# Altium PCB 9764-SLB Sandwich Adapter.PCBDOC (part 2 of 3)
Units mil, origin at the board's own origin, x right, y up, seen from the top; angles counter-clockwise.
Board outline 5593.84 x 1511.98 mil, 8 copper layers (Top Layer, MidLayer1, MidLayer2, MidLayer3, MidLayer4, MIdLayer5, MidLayer6, Bottom Layer); 137 components, 228 nets, 1508 pads, 0 vias.
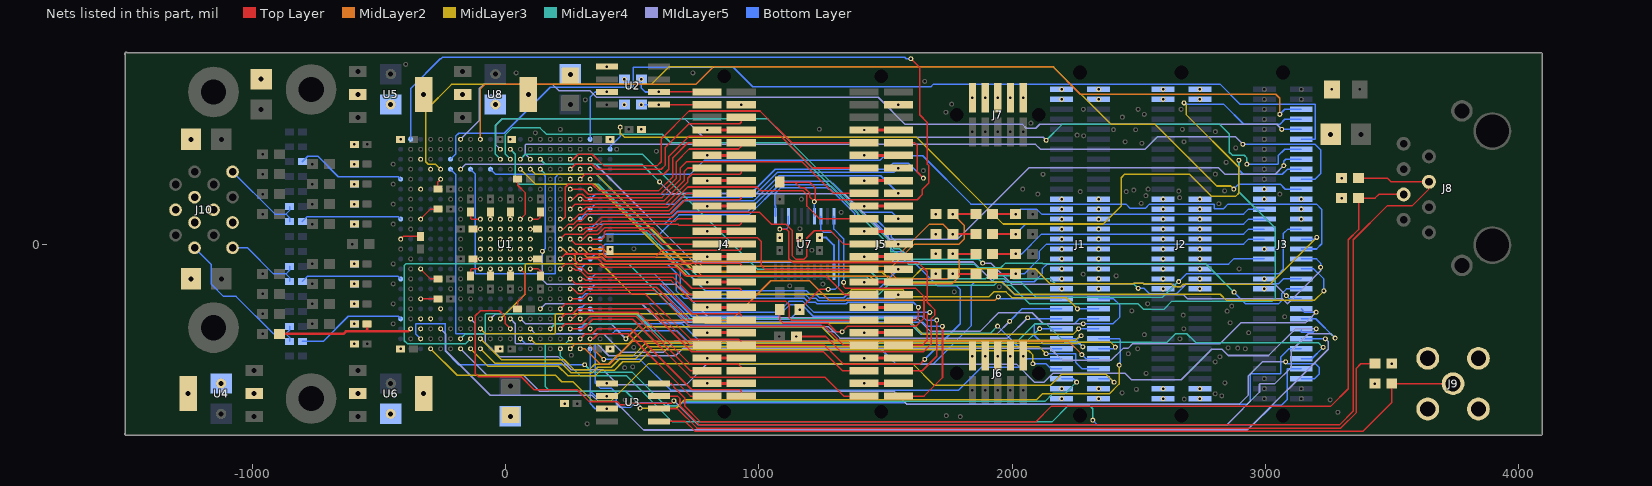
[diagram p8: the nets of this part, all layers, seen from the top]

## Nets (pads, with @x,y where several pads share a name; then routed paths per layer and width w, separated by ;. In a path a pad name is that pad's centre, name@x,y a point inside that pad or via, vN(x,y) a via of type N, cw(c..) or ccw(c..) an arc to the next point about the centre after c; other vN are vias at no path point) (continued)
AVCCAUX8: C28.1 L22.1 U1.B20 | length 557.6
  Top Layer w10: L22.1@-891.73,-354.33 -639.76,-354.33 -629.92,-344.49 -551.18,-344.49 ; C28.1@-545.87,-314.96 -545.87,-339.17 -551.18,-344.49 ; U1.B20@-374.02,-334.65 -383.86,-344.49 -551.18,-344.49
B: C43.1 C44.1 J10.1 | length 350.8
  Bottom Layer w6: J10.1@-1076.85,285 -909.96,118.11 -866.14,118.11 ; C43.1@-851.77,88.58 -851.77,103.74 -866.14,118.11 ; C44.1@-851.77,147.64 -851.77,132.48 -866.14,118.11
BCO+: pad.0@1765.75,39.37 R7.2 R11.2 U1.Y12 | length 1619.5
  Top Layer w8: R11.2@1765.75,39.37 R7.2@1856.3,39.37
  MidLayer2 w6: U1.Y12@334.65,-19.69 385.83,-19.69 405.51,-39.37 748.03,-39.37 777.56,-68.9 1525.59,-68.9 1673.23,78.74 1726.38,78.74 pad.0@1765.75,39.37
BCO-: pad.0@1765.75,118.11 R6.2 R9.2 U1.W12 | length 1796.9
  Top Layer w8: R9.2@1765.75,118.11 R6.2@1856.3,118.11
  MidLayer2 w6: U1.W12@295.28,-19.69 307.09,-19.69 326.77,-39.37 387.8,-39.37 401.58,-53.15 742.13,-53.15 777.56,-88.58 1525.59,-88.58 1614.17,0 1791.34,0 1811.02,19.69 1811.02,72.83 pad.0@1765.75,118.11
C: C47.1 C48.1 J10.7 | length 324.4
  Bottom Layer w6: J10.7@-1076.85,-15 -1018.46,-15 -915.35,-118.11 -866.14,-118.11 ; C47.1@-851.77,-147.64 -851.77,-132.48 -866.14,-118.11 ; C48.1@-851.77,-88.58 -851.77,-103.74 -866.14,-118.11
CCLOCK: pad.0@1082.68,59.06 pad.0@1148.47,-365 R23.1 U1.W20 U7.3 | length 2570.5
  Top Layer w6: pad.0@1082.68,59.06 1108.27,59.06 1118.11,49.21 1118.11,-58.07 1134.84,-74.8 1629.92,-74.8 1665,-109.88 1665,-230 1695,-260 1695,-280 1680,-295 1680,-395 1649.8,-425.2 1324.8,-425.2 1297.24,-397.64 1264.61,-365 R23.1@1148.47,-365
  Bottom Layer w6: U1.W20@295.28,-334.65 314.96,-314.96 696.85,-314.96 771.65,-389.76 1123.7,-389.76 pad.0@1148.47,-365 ; pad.0@1082.68,59.06 1109.25,59.06 1117.13,66.93 U7.3@1117.13,109.25
CLK+: pad.0@1765.75,-118.11 R8.2 R10.2 U1.V12 | length 1657.5
  Top Layer w8: R10.2@1765.75,-118.11 R8.2@1856.3,-118.11
  MidLayer2 w6: U1.V12@255.91,-19.69 267.72,-19.69 287.4,-39.37 309.06,-39.37 322.84,-53.15 383.86,-53.15 397.64,-66.93 736.22,-66.93 777.56,-108.27 1515.75,-108.27 1545.28,-137.8 1746.06,-137.8 pad.0@1765.75,-118.11
CLK-: pad.0@1765.75,-39.37 R5.2 R12.2 U1.U12 | length 1845.4
  Top Layer w8: R12.2@1765.75,-39.37 R5.2@1856.3,-39.37
  MidLayer2 w6: U1.U12@216.54,-19.69 228.35,-19.69 248.03,-39.37 267.72,-39.37 275.59,-47.24 275.59,-66.93 287.4,-78.74 393.7,-78.74 395.67,-80.71 730.32,-80.71 777.56,-127.95 1515.75,-127.95 1545.28,-157.48 1761.81,-157.48 1791.34,-127.95 1791.34,-64.96 pad.0@1765.75,-39.37
D: C53.1 C54.1 J10.14 | length 617.4
  Bottom Layer w6: J10.14@-1226.85,-15 -1161.42,-80.43 -1161.42,-157.48 -1112.2,-206.69 -1062.99,-206.69 -915.35,-354.33 -866.14,-354.33 ; C53.1@-851.77,-383.86 -851.77,-368.7 -866.14,-354.33 ; C54.1@-851.77,-324.8 -851.77,-339.96 -866.14,-354.33
DONE: pad.0@1328.74,-346.46 pad.0@1334.65,-151.57 R24.1 U1.Y18 U7.10 | length 2396.3
  Top Layer w6: R24.1@1082.68,-258.46 1082.68,-300.2 1095.47,-312.99 1272.64,-312.99 1306.1,-346.46 pad.0@1328.74,-346.46 1350.39,-324.8 1620.5,-324.8 1652,-293.31 1652,-207.12 1620.08,-175.2 1342.52,-175.2 1334.65,-167.32 pad.0@1334.65,-151.57
  Bottom Layer w6: U1.Y18@334.65,-255.91 354.33,-275.59 674.72,-275.59 720.37,-321.24 1246.44,-321.24 1271.65,-346.46 pad.0@1328.74,-346.46 ; U7.10@1296.26,109.25 1296.26,58.74 1334.65,20.35 pad.0@1334.65,-151.57
ERRA: J4.23 U1.V4 | length 828.2
  Top Layer w6: U1.V4@255.91,295.28 275.59,314.96 342.52,314.96 362.21,295.28 615.28,295.28 630,310 630,380 725,475 925,475 930.65,480.65 J4.23@930.65,500
ERRB: J4.36 U1.W13 | length 517.3
  Top Layer w6: U1.W13@295.28,-59.06 366.54,-59.06 386.22,-78.74 683.74,-78.74 705,-100 J4.36@795.65,-100
ERRC: J5.38 U1.V10 | length 1435.4
  Top Layer w6: U1.V10@257.09,60.24 U1.V10@255.91,59.06 268.11,59.06 287.8,78.74 352.76,78.74 380.32,106.3 661.3,106.3 680.98,125.98 1001.97,125.98 1049.21,78.74 1106.3,78.74 1132.87,52.17 1132.87,-47.24 1146.65,-61.02 1177.17,-61.02 1188.98,-49.21 1188.98,22.64 1218.5,52.17 1282.48,52.17 1314.96,19.69 1334.65,0 J5.38@1415.65,0
ERRD: J5.3 pad.0@1702,-300 U1.Y16 | length 1790.5
  Top Layer w6: J5.3@1550.65,-500 1645,-500 1702,-443 pad.0@1702,-300
  Bottom Layer w6: U1.Y16@334.65,-177.17 354.33,-157.48 607.48,-157.48 634.85,-184.85 ; 634.89,-184.85 735.04,-285 1077.76,-285 1123.58,-239.17 1169.29,-239.17 1215.12,-285 1645,-285 1660,-300 pad.0@1702,-300
GND: C1.2 C2.2 C3.2 C4.2 C5.2 C6.2 C7.2 C8.2 C9.2 C10.2 C11.2 C12.2 C13.2 C14.2 C15.2 C16.2 C17.2 C18.2 C19.2 C22.2 C25.2 C28.2 C29.2 C30.2 C31.2 C32.2 C33.2 C34.2 C35.2 C36.2 C68.2 C69.2 C70.2 C85.2 C86.2 C87.2 C88.2 C89.2 C90.2 C91.2 C92.2 C93.2 C94.2 C95.2 C96.2 C97.2 C98.2 C99.2 C100.2 C101.2 C102.2 C103.2 C104.2 C105.2 C106.2 C109.2 C110.2 C111.2 C112.2 D2.2 D3.2 D4.2 J1.1 J1.2 J1.3 J1.4 J1.23 J1.24 J1.25 J1.26 J1.27 J1.28 J1.29 J1.30 J1.31 J1.32 J1.33 J1.34 J1.35 J1.36 J1.37 J1.38 J1.39 J1.40 J1.41 J1.42 J1.61 J1.62 J1.63 J1.64 J2.1 J2.2 J2.3 J2.4 J2.23 J2.24 J2.25 J2.26 J2.27 J2.28 J2.29 J2.30 J2.31 J2.32 J2.33 J2.34 J2.35 J2.36 J2.37 J2.38 J2.39 J2.40 J2.41 J2.42 J2.61 J2.62 J2.63 J2.64 J3.24 J3.26 J3.32 J3.37 J3.39 J3.41 J3.42 J3.44 J4.2 J4.4 J4.6 J4.8 J4.10 J4.12 J4.14 J4.16 J4.18 J4.20 J4.22 J4.24 J4.27 J4.29 J4.31 J4.33 J4.35 J4.37 J4.39 J4.41 J4.43 J4.45 J4.47 J5.2 J5.4 J5.6 J5.8 J5.10 J5.12 J5.14 J5.16 J5.18 J5.20 J5.22 J5.24 J5.27 J5.29 J5.31 J5.33 J5.35 J5.37 J5.39 J5.41 J5.43 J5.45 J5.47 J6.6 J6.7 J6.8 J6.9 J6.10 J7.6 J7.7 J7.8 J7.9 J7.10 J9.2 J10.4 J10.5 J10.10 J10.11 J10.12 pad.0@19.68,-680.08 pad.0@90.55,590.55 pad.0@233.27,-629.92 pad.0@255.91,669.29 pad.0@400.79,700 pad.0@400.79,-550 pad.0@469.69,550 pad.0@469.69,650 pad.0@536.81,452.76 pad.0@795.65,50 pad.0@795.65,150 pad.0@795.65,250 pad.0@795.65,350 pad.0@795.65,450 pad.0@795.65,-50 pad.0@795.65,-150 pad.0@795.65,-250 pad.0@795.65,-350 pad.0@795.65,-450 pad.0@795.65,-550 pad.0@930.65,550 pad.0@1082.68,25 pad.0@1161.42,25 pad.0@1240.16,25 pad.0@1415.65,50 pad.0@1415.65,150 pad.0@1415.65,250 pad.0@1415.65,350 pad.0@1415.65,450 pad.0@1415.65,-50 pad.0@1415.65,-150 pad.0@1415.65,-250 pad.0@1415.65,-350 pad.0@1415.65,-450 pad.0@1415.65,-550 pad.0@1550.65,550 pad.0@1698.82,39.37 pad.0@1698.82,118.11 pad.0@1698.82,-39.37 pad.0@1698.82,-118.11 pad.0@1843.15,577.5 pad.0@1843.15,-442.5 pad.0@1893.15,577.5 pad.0@1893.15,-442.5 pad.0@1943.15,577.5 pad.0@1943.15,-442.5 pad.0@1993.15,577.5 pad.0@1993.15,-442.5 pad.0@2043.15,577.5 pad.0@2043.15,-442.5 pad.0@2195.32,19.69 pad.0@2195.32,59.06 pad.0@2195.32,98.43 pad.0@2195.32,137.8 pad.0@2195.32,177.17 pad.0@2195.32,570.87 pad.0@2195.32,610.24 pad.0@2195.32,-19.68 pad.0@2195.32,-59.05 pad.0@2195.32,-98.42 pad.0@2195.32,-137.79 pad.0@2195.32,-177.16 pad.0@2195.32,-570.87 pad.0@2195.32,-610.24 pad.0@2340.98,19.69 pad.0@2340.98,59.06 pad.0@2340.98,98.43 pad.0@2340.98,137.8 pad.0@2340.98,177.17 pad.0@2340.98,570.87 pad.0@2340.98,610.24 pad.0@2340.98,-19.68 pad.0@2340.98,-59.05 pad.0@2340.98,-98.42 pad.0@2340.98,-137.79 pad.0@2340.98,-177.16 pad.0@2340.98,-570.87 pad.0@2340.98,-610.24 pad.0@2595.32,19.69 pad.0@2595.32,59.06 pad.0@2595.32,98.43 pad.0@2595.32,137.8 pad.0@2595.32,177.17 pad.0@2595.32,570.87 pad.0@2595.32,610.24 pad.0@2595.32,-19.68 pad.0@2595.32,-59.05 pad.0@2595.32,-98.42 pad.0@2595.32,-137.79 pad.0@2595.32,-177.16 pad.0@2595.32,-570.87 pad.0@2595.32,-610.24 pad.0@2740.98,19.69 pad.0@2740.98,59.06 pad.0@2740.98,98.43 pad.0@2740.98,137.8 pad.0@2740.98,177.17 pad.0@2740.98,570.87 pad.0@2740.98,610.24 pad.0@2740.98,-19.68 pad.0@2740.98,-59.05 pad.0@2740.98,-98.42 pad.0@2740.98,-137.79 pad.0@2740.98,-177.16 pad.0@2740.98,-570.87 pad.0@2740.98,-610.24 pad.0@2995.32,177.17 pad.0@2995.32,216.54 pad.0@2995.32,-19.68 pad.0@2995.32,-137.79 pad.0@2995.32,-177.16 pad.0@3140.98,98.43 pad.0@3140.98,137.8 pad.0@3140.98,177.17 pad.0@3256.93,433.07 pad.0@3261.93,610.24 pad.0@3300.09,181.19 pad.0@3300.09,259.93 pad.0@3431.1,-551.18 pad.0@3498.03,-472.44 pad.0@-39.37,550.24 pad.0@-169.29,590.55 pad.0@-322.83,590.55 pad.0@-322.83,-590.55 pad.0@-452.76,550.24 pad.0@-452.76,-670.24 pad.0@-582.68,590.55 pad.0@-582.68,-590.55 pad.0@-595.87,78.74 pad.0@-595.87,157.48 pad.0@-595.87,236.22 pad.0@-595.87,314.96 pad.0@-595.87,393.7 pad.0@-595.87,-78.74 pad.0@-595.87,-157.48 pad.0@-595.87,-236.22 pad.0@-595.87,-314.96 pad.0@-595.87,-393.7 pad.0@-964.57,650.55 pad.0@-992.13,-590.55 pad.0@-1122.05,-550.24 pad.0@-1241.1,413.39 pad.0@-1241.1,-137.8 pad.0@-1251.97,-590.55 R9.1 R10.1 R11.1 R12.1 R14.2 R15.2 R16.2 R17.2 R18.2 R19.2 U1.A1 U1.A11 U1.A22 U1.AB1 U1.AB12 U1.AB22 U1.C3 U1.C6 U1.C9 U1.C14 U1.C17 U1.C19 U1.C20 U1.D4 U1.D19 U1.E5 U1.E18 U1.J9 U1.J10 U1.J11 U1.J12 U1.J13 U1.J14 U1.K9 U1.K10 U1.K11 U1.K12 U1.K13 U1.K14 U1.L9 U1.L10 U1.L11 U1.L12 U1.L13 U1.L14 U1.L22 U1.M1 U1.M9 U1.M10 U1.M11 U1.M12 U1.M13 U1.M14 U1.N9 U1.N10 U1.N11 U1.N12 U1.N13 U1.N14 U1.P9 U1.P10 U1.P11 U1.P12 U1.P13 U1.P14 U1.V5 U1.V18 U1.W3 U1.W4 U1.W19 U1.Y3 U1.Y4 U1.Y5 U1.Y6 U1.Y9 U1.Y14 U1.Y17 U1.Y20 U2.5 U3.5 U4.2 U4.4 U5.2 U5.4 U6.2 U6.4 U7.11 U8.2 U8.4 | length 4354.1
  Top Layer w6: U1.A11@-413.39,19.69 -402.76,30.32 C106.2@-334.65,30.32 ; U1.C17@-334.65,-216.54 C36.2@-266.54,-216.54 ; U1.C14@-334.65,-98.43 -295.28,-137.8 C104.2@-266.54,-137.8 ; U1.C9@-334.65,98.43 -295.28,137.8 C105.2@-266.54,137.8 ; C31.2@-266.54,216.54 -266.54,245.28 U1.E5@-255.91,255.91 ; C30.2@-137.79,-127.17 -137.79,-100.79 -135.43,-98.43 U1.J14@-98.43,-98.43 ; C29.2@-137.79,127.17 -137.79,100.79 -135.43,98.43 U1.J9@-98.43,98.43 ; C95.2@-127.17,-59.06 U1.J13@-98.43,-59.06 ; C96.2@-127.17,59.06 U1.J10@-98.43,59.06 ; C92.2@-59.05,-127.17 U1.K14@-59.06,-98.43 ; U1.K9@-59.06,98.43 C98.2@-59.05,127.17 ; C91.2@19.69,-127.17 U1.M14@19.69,-98.43 ; U1.M9@19.69,98.43 C97.2@19.69,127.17 ; C34.2@48.43,-255.91 48.43,-227.17 78.74,-196.85 78.74,-118.11 U1.N14@59.06,-98.43 ; C35.2@48.43,255.91 48.43,231.57 78.74,201.26 78.74,118.11 U1.N9@59.06,98.43 ; U1.P14@98.43,-98.43 130.32,-98.43 137.8,-105.91 C32.2@137.8,-127.17 ; U1.P13@98.43,-59.06 C99.2@127.17,-59.06 ; U1.P10@98.43,59.06 C102.2@127.17,59.06 ; U1.P9@98.43,98.43 130.32,98.43 137.8,105.91 C33.2@137.8,127.17
  Top Layer w12: J4.27@795.65,-550 J4.2@930.65,-550 ; J4.29@795.65,-450 J4.4@930.65,-450 ; J4.31@795.65,-350 J4.6@930.65,-350 ; J4.33@795.65,-250 J4.8@930.65,-250 ; J4.35@795.65,-150 J4.10@930.65,-150 ; J4.37@795.65,-50 J4.12@930.65,-50 ; J4.39@795.65,50 J4.14@930.65,50 ; J4.41@795.65,150 J4.16@930.65,150 ; J4.43@795.65,250 J4.18@930.65,250 ; J4.45@795.65,350 J4.20@930.65,350 ; J4.47@795.65,450 J4.22@930.65,450 ; J5.27@1415.65,-550 J5.2@1550.65,-550 ; J5.29@1415.65,-450 J5.4@1550.65,-450 ; J5.31@1415.65,-350 J5.6@1550.65,-350 ; J5.33@1415.65,-250 J5.8@1550.65,-250 ; J5.35@1415.65,-150 J5.10@1550.65,-150 ; J5.37@1415.65,-50 J5.12@1550.65,-50 ; J5.39@1415.65,50 J5.14@1550.65,50 ; J5.41@1415.65,150 J5.16@1550.65,150 ; J5.43@1415.65,250 J5.18@1550.65,250 ; J5.45@1415.65,350 J5.20@1550.65,350 ; J5.47@1415.65,450 J5.22@1550.65,450
  Bottom Layer w8: pad.0@1240.16,25 1266.73,25 1296.26,-4.53 U7.11@1296.26,-109.25
IDLEA: J4.21 U1.V6 | length 813.5
  Top Layer w6: U1.V6@255.91,216.54 307.48,216.54 327.17,196.85 611.85,196.85 675,260 675,325 725,375 920,375 930.65,385.65 J4.21@930.65,400
IDLEB: J4.34 U1.V14 | length 581.8
  Top Layer w6: U1.V14@255.91,-98.43 271.65,-98.43 277.56,-104.33 295.28,-104.33 321.85,-130.91 660.91,-130.91 730,-200 J4.34@795.65,-200
IDLEC: J5.36 U1.W11 | length 1263.1
  Top Layer w6: U1.W11@295.28,19.69 307.48,19.69 327.17,39.37 366.54,39.37 392.13,64.96 582.09,64.96 622.05,25 995,25 1010,10 1010,-85 1025,-100 J5.36@1415.65,-100
IDLED: J5.1 pad.0@1725,-325 U1.W18 | length 1881.2
  Top Layer w6: J5.1@1550.65,-600 1651.97,-600 1725,-526.97 pad.0@1725,-325
  Bottom Layer w6: U1.W18@295.28,-255.91 314.96,-236.22 652.32,-236.22 725.34,-309.24 1649.24,-309.24 1665,-325 pad.0@1725,-325
KCHA: J4.46 U1.U9 | length 839.2
  Top Layer w6: U1.U9@216.54,98.43 228.35,98.43 236.22,106.3 236.22,224.41 248.03,236.22 342.52,236.22 369.09,209.65 604.65,209.65 660,265 660,340 720,400 J4.46@795.65,400
KCHB: J4.11 U1.U13 | length 758.7
  Top Layer w6: U1.U13@216.54,-59.06 236.22,-39.37 364.57,-39.37 391.14,-65.94 690.95,-65.94 700,-75 925,-75 930.65,-80.65 J4.11@930.65,-100
KCHC: J5.13 pad.0@1550.65,0 U1.AA11 | length 1374.4
  Bottom Layer w6: U1.AA11@374.02,19.69 393.7,39.37 609.37,39.37 685,115 961.46,115 1080.71,234.25 1272.72,234.25 1278.25,228.72 1287.19,228.72 1391,124.91 1391,115.97 1404.97,102 1459.97,102 1522,39.97 1522,28.65 pad.0@1550.65,0
KCHD: J5.26 U1.V20 | length 1300.6
  Top Layer w6: U1.V20@255.91,-334.65 307.09,-334.65 344.49,-297.24 502.24,-297.24 730,-525 1260,-525 1335,-600 J5.26@1415.65,-600
LOC_C\S\: J3.59 pad.0@3056.15,512 U1.J1 | length 3596.8
  MidLayer2 w6: U1.J1@-98.43,413.39 -98.43,612.5 -80.08,630.84 751.99,630.84 820.15,699 2161.05,699 2269.05,591 3040.15,591 3056.15,575 pad.0@3056.15,512
  Bottom Layer w6: pad.0@3056.15,512 3075.65,531.5 J3.59@3140.98,531.5
LOC_R/W\: J3.57 pad.0@453.15,461 pad.0@2678.15,557 U1.AB2 | length 3856.3
  MidLayer3 w6: pad.0@453.15,461 453.15,437.5 468.65,422 1621.15,422 1964.15,79 2359.15,79 2430.15,150 2430.15,261.5 2444.65,276 2698.65,276 2785.65,189 2883.15,189 2894.15,200 2894.15,302.98 2686.15,510.98 2686.15,549 pad.0@2678.15,557
  Bottom Layer w6: U1.AB2@413.39,374.02 413.39,385.01 453.15,424.78 pad.0@453.15,461 ; pad.0@2678.15,557 2684.15,551 2835.77,551 2914.15,472.62 3056.65,472.62 3076.15,492.13 J3.57@3140.98,492.13
LOCADD_0: J3.55 pad.0@3063.91,452.76 U1.G1 | length 3568.4
  MIdLayer5 w6: U1.G1@-177.17,413.39 -103.85,486.7 -103.85,613 -86.85,630 186.15,630 211.31,604.84 333.99,604.84 359.84,579 1471.15,579 1578.15,472 2040.96,472 2055.96,457 2092.84,457 2108.68,472.84 3043.82,472.84 pad.0@3063.91,452.76
  Bottom Layer w6: pad.0@3063.91,452.76 J3.55@3140.98,452.76
LOCADD_1: J3.53 U1.F3 | length 3909.3
  Bottom Layer w6: U1.F3@-216.54,334.65 -196.85,354.33 -196.85,425 -184.35,437.5 -4.85,437.5 176.65,619 502.15,619 505.15,622 505.15,697 506.15,698 899.15,698 976.15,621 1679.15,621 1689.15,631 2820.15,631 2900.15,551 3195.15,551 3196.15,550 3196.15,414.39 3195.15,413.39 J3.53@3140.98,413.39
LOCADD_2: J3.51 pad.0@2134.15,409.5 pad.0@2926.49,315 U1.L2 | length 3518.2
  MIdLayer5 w6: U1.L2@-19.69,374.02 -38.85,393.18 -38.85,469.5 -14.51,493.84 708.31,493.84 781.15,421 2122.65,421 pad.0@2134.15,409.5
  MidLayer4 w6: pad.0@2134.15,409.5 2196.65,472 2818.84,472 2857.15,433.69 2857.15,362.5 2869.65,350 2915.7,350 2926.49,339.21 pad.0@2926.49,315
  Bottom Layer w6: pad.0@2926.49,315 3048.59,315 3049.59,316 3049.59,347.96 3075.65,374.02 J3.51@3140.98,374.02
LOCADD_3: J3.49 pad.0@608.15,245 pad.0@3072.15,309.59 U1.R3 | length 3295.8
  MIdLayer5 w6: pad.0@608.15,245 655.15,198 1338.15,198 1517.15,19 1784.15,19 2066.24,301.09 2813.93,301.09 2839.43,275.59 3038.15,275.59 pad.0@3072.15,309.59
  MidLayer4 w6: U1.R3@137.8,334.65 157.44,315 538.15,315 pad.0@608.15,245
  Bottom Layer w6: pad.0@3072.15,309.59 3072.15,326.65 3080.15,334.65 J3.49@3140.98,334.65
LOCADD_4: J3.47 pad.0@2894.65,330.5 U1.M2 | length 4303.6
  MidLayer4 w6: U1.M2@19.69,374.02 39.15,354.55 39.15,251 54.15,236 366.15,236 801.15,-199 1473.15,-199 1509.15,-163 1928.31,-163 1941.65,-149.66 1956.65,-149.66 1969.99,-163 1995.15,-163 2068.15,-236 2496.81,-236 2519.15,-258.34 2598.09,-258.34 2631.27,-225.16 3025.65,-225.16 3039.15,-211.66 3039.15,62 2894.65,206.5 pad.0@2894.65,330.5
  Bottom Layer w6: pad.0@2894.65,330.5 2894.65,293 2912.24,275.41 3066.28,275.41 3086.15,295.28 J3.47@3140.98,295.28
LOCADD_5: J3.45 pad.0@2910.65,393.52 U1.P3 | length 3434
  MIdLayer5 w6: U1.P3@98.43,334.65 78.15,354.92 78.15,391.08 80.07,393 2092.44,393 2111.75,373.7 2524.49,373.7 2573.8,423 2881.17,423 pad.0@2910.65,393.52
  Bottom Layer w6: pad.0@2910.65,393.52 3195.15,393.52 3217.99,370.67 3217.99,278.75 3195.15,255.91 J3.45@3140.98,255.91
LOCADD_6: J3.43 pad.0@2874.65,217 U1.E4 | length 4016.8
  MidLayer3 w6: U1.E4@-255.91,295.28 -275.63,315 -304.85,315 -314.85,325 -314.85,528 -212.85,630 575.82,630 644.82,699 2163.55,699 2389.71,472.84 2563.4,472.84 2807.24,229 2862.65,229 pad.0@2874.65,217
  Bottom Layer w6: pad.0@2874.65,217 2894.05,236.4 3058.15,236.4 3078.02,216.54 J3.43@3140.98,216.54
LOCBUS_0: J3.35 pad.0@2657.15,-148 U1.R4 | length 3416.8
  MidLayer2 w6: pad.0@2656.15,-147 pad.0@2657.15,-148
  MidLayer4 w6: U1.R4@137.8,295.28 157.07,276 355.15,276 761.15,-130 1426.15,-130 1445.15,-149 1918.31,-149 1929.65,-137.66 1968.65,-137.66 1980.99,-150 2034.15,-150 2094.15,-210 2593.15,-210 pad.0@2656.15,-147
  Bottom Layer w6: pad.0@2657.15,-148 2687.15,-118 3052.15,-118 3070.15,-100 3070.15,41.06 3088.15,59.06 J3.35@3140.98,59.06
LOCBUS_1: J3.33 pad.0@3202.15,26 U1.P4 | length 3472.9
  MidLayer3 w6: U1.P4@98.43,295.28 117.7,276 359.99,276 746.99,-111 1487.15,-111 1512.15,-136 1605.15,-136 1643.15,-98 2090.65,-98 2149.65,-157 2476.5,-157 2478.5,-155 2515.97,-155 2517.97,-157 2626.94,-157 2637.94,-168 2665.28,-168 2675.28,-158 3018.15,-158 pad.0@3202.15,26
  Bottom Layer w6: J3.33@3140.98,19.69 3195.84,19.69 pad.0@3202.15,26
LOCBUS_2: J3.31 U1.H4 | length 4525.9
  Bottom Layer w6: U1.H4@-137.8,295.28 -118.85,276.33 -118.85,-116 -116.85,-118 195.15,-118 197.15,-116 197.15,263.5 209.65,276 730.15,276 784.15,330 1477.65,330 1495.65,348 1647,348 1837.52,157.48 2448.98,157.48 2465.46,141 2525.67,141 2542.15,157.48 2795.64,157.48 2797.12,156 2797.12,141.18 2798.31,140 2834.84,140 2852.32,157.48 3201.17,157.48 3222.15,136.5 3222.15,1 3201.47,-19.68 J3.31@3140.98,-19.68
LOCBUS_3: J3.29 pad.0@3217.1,-92 U1.G4 | length 3797.3
  MIdLayer5 w6: U1.G4@-177.17,295.28 -157.44,315 356.15,315 742.15,-71 1846.15,-71 1924.15,-149 1960.14,-149 2011.14,-200 2676.21,-200 2691.4,-215.19 3066.19,-215.19 3086,-235 3088,-235 3217.1,-105.9 pad.0@3217.1,-92
  Bottom Layer w6: J3.29@3140.98,-59.05 3201.15,-59.05 3217.1,-75 pad.0@3217.1,-92
LOCBUS_4: J3.27 pad.0@3230.28,-185.19 U1.N4 | length 3554
  MidLayer3 w6: U1.N4@59.06,295.28 118.33,236 354.15,236 717.31,-127.16 1439.31,-127.16 1462.15,-150 1961.22,-150 2009.22,-198 2820.96,-198 2845.81,-222.84 3192.63,-222.84 pad.0@3230.28,-185.19
  Bottom Layer w6: J3.27@3140.98,-98.42 3190.15,-98.42 3230.28,-138.56 pad.0@3230.28,-185.19
LOCBUS_5: J3.25 pad.0@2497.15,-175 U1.N3 | length 3351.8
  MidLayer4 w6: U1.N3@59.06,334.65 78.41,354 541.15,354 995.15,-100 1432.15,-100 1469.15,-137 1894.96,-137 1906.31,-125.66 1991.99,-125.66 2004.34,-138 2151.15,-138 2170.15,-157 2479.15,-157 pad.0@2497.15,-175
  Bottom Layer w6: pad.0@2497.15,-175 2520.49,-175 2542.15,-196.66 2648.15,-196.66 2687.52,-157.3 3050.15,-157.3 3069.65,-137.79 J3.25@3140.98,-137.79
LOCBUS_6: J3.23 pad.0@2875.65,-190 U1.M3 | length 3613.2
  MidLayer4 w6: U1.M3@19.69,334.65 0.15,354.18 0.15,432 26.15,458 136.84,458 161.84,433 619.15,433 652.15,400 1111.15,400 1520.15,-9 1520.15,-29.84 1521.15,-30.84 1541.99,-30.84 1590.15,-79 1849.62,-79 1864.62,-94 1954.94,-94 1973.94,-75 2119.55,-75 2122.55,-78 2763.65,-78 pad.0@2875.65,-190
  Bottom Layer w6: pad.0@2875.65,-190 2921.9,-236.25 3050.65,-236.25 3063.15,-223.75 3063.15,-196.16 3082.15,-177.16 J3.23@3140.98,-177.16
LOCBUS_7: J3.21 pad.0@1883.15,-75 pad.0@3082.15,-204 U1.L3 | length 3645.5
  MIdLayer5 w6: pad.0@1883.15,-75 1915.45,-75 1998.45,-158 2477.28,-158 2480.28,-155 2515.75,-155 2518.75,-158 2638.59,-158 2648.59,-168 2674.93,-168 2684.93,-158 3036.15,-158 pad.0@3082.15,-204
  MidLayer4 w6: U1.L3@-19.69,334.65 -39.85,354.81 -39.85,466.5 -12.51,493.84 1034.31,493.84 1532.15,-4 1532.15,-17.84 1533.15,-18.84 1554.99,-18.84 1596.15,-60 1868.15,-60 pad.0@1883.15,-75
  Bottom Layer w6: pad.0@3082.15,-204 3094.68,-216.53 J3.21@3140.98,-216.53
LOCBUS_8: J3.19 pad.0@3199.15,-269 U1.M19 | length 3458.3
  MIdLayer5 w6: U1.M19@19.69,-295.28 39.15,-314.74 39.15,-391 41.15,-393 360.15,-393 408.15,-441 671.15,-441 701.15,-411 2150.15,-411 2197.15,-458 2391.43,-458 2437.5,-411.93 2456.72,-411.93 2474.65,-394 2820.15,-394 2903.15,-311 3157.15,-311 pad.0@3199.15,-269
  Bottom Layer w6: J3.19@3140.98,-255.91 3154.08,-269 pad.0@3199.15,-269
LOCBUS_9: J3.17 pad.0@665.15,-619 pad.0@3274.15,-371 U1.M20 | length 4288.5
  Top Layer w6: U1.M20@19.69,-334.65 0.15,-315.11 0.15,-287.5 -24.35,-263 -98.35,-263 -118.85,-283.5 -118.85,-511.5 -106.35,-524 62.15,-524 113.15,-575 283.15,-575 330.15,-622 441.15,-622 454.15,-635 485.15,-635 492.15,-628 656.15,-628 pad.0@665.15,-619
  MIdLayer5 w6: pad.0@665.15,-619 760.15,-714 2846.47,-714 2976.15,-584.32 2976.15,-553.32 2978.47,-551 3037.15,-551 3101.15,-487 3101.15,-421 3168.15,-354 3257.15,-354 pad.0@3274.15,-371
  Bottom Layer w6: J3.17@3140.98,-295.28 3198.43,-295.28 pad.0@3274.15,-371
LOCBUS_10: J3.15 pad.0@3200.15,-335 U1.H19 | length 3758.3
  MIdLayer5 w6: U1.H19@-137.8,-295.28 -118.85,-314.22 -118.85,-352 -115.85,-355 -79.85,-355 -78.85,-356 -78.85,-390 -24.62,-444.23 207.77,-444.23 259.54,-496 385.15,-496 445.15,-556 712.15,-556 794.15,-474 2016.65,-474 2088.15,-545.5 2125.65,-545.5 2161.18,-509.97 2445.12,-509.97 2471.15,-536 2667.16,-536 2788.09,-415.07 2828.15,-415.07 2853.08,-440 3012.15,-440 3117.15,-335 pad.0@3200.15,-335
  Bottom Layer w6: J3.15@3140.98,-334.65 3140.98,-347 3141.98,-348 3187.15,-348 pad.0@3200.15,-335
LOCBUS_11: J3.13 pad.0@3236.02,-374.02 U1.E20 | length 3980
  MIdLayer5 w6: U1.E20@-255.91,-334.65 -235.85,-354.7 -235.85,-421 -59.85,-597 342.15,-597 365.15,-620 431.15,-620 545.15,-734 2928.09,-734 3247.15,-414.94 3247.15,-385.14 pad.0@3236.02,-374.02
  Bottom Layer w6: J3.13@3140.98,-374.02 pad.0@3236.02,-374.02
LOCBUS_12: J3.11 U1.N21 | length 3518.9
  Bottom Layer w6: U1.N21@59.06,-374.02 78.04,-393 352.15,-393 354.15,-395 354.15,-549 375.15,-570 419.65,-570 437.15,-587.5 437.15,-630.5 450.65,-644 494.15,-644 512.15,-626 634.46,-626 646.46,-638 683.35,-638 694.35,-627 1579.15,-627 1585.15,-633 2925.65,-633 2940.15,-618.5 2940.15,-512.99 2941.15,-511.99 3058.15,-511.99 3059.15,-510.99 3059.15,-447 3092.76,-413.39 J3.11@3140.98,-413.39
LOCBUS_13: J3.9 pad.0@3227.15,-408 U1.G21 | length 3737.5
  MidLayer4 w6: U1.G21@-177.17,-374.02 -158.15,-355 -80.85,-355 -78.85,-353 -78.85,-277 -76.85,-275 516.14,-275 628.14,-387 2018.31,-387 2091.31,-314 2133.15,-314 2206.15,-387 2612.15,-387 2645.15,-354 2689.15,-354 2725.15,-390 3209.15,-390 pad.0@3227.15,-408
  Bottom Layer w6: J3.9@3140.98,-452.76 3182.39,-452.76 pad.0@3227.15,-408
LOCBUS_14: J3.7 pad.0@2318.15,-695 U1.U22 | length 3307.5
  MidLayer4 w6: U1.U22@216.54,-413.39 216.54,-441.78 293.81,-519.05 476.96,-519.05 659.92,-702 2157.15,-702 2221.65,-637.5 2305.65,-637.5 2318.15,-650 pad.0@2318.15,-695
  Bottom Layer w6: pad.0@2318.15,-695 2337.15,-714 2950.15,-714 3028.15,-636 3063.15,-636 3086.15,-613 3086.15,-493.13 3087.15,-492.13 J3.7@3140.98,-492.13
LOCBUS_15: J3.5 pad.0@3079.15,-465 U1.G22 | length 3707.5
  MIdLayer5 w6: U1.G22@-177.17,-413.39 -72.55,-518 71.15,-518 134.31,-581.16 1533.31,-581.16 1585.15,-633 2895.15,-633 2932.41,-595.74 2932.41,-520.24 2987.65,-465 pad.0@3079.15,-465
  Bottom Layer w6: pad.0@3079.15,-465 3086.41,-472.26 3196.91,-472.26 3212.15,-487.5 3212.15,-512.5 3193.15,-531.5 J3.5@3140.98,-531.5
NetJ8_4: J8.4 R17.1 U3.3 | length 4197.4
  Top Layer w6: U3.3@605.51,-600 678.74,-600 688.98,-610.24 688.98,-638 765.17,-714.19 3291.72,-714.19 3346.46,-659.45 3346.46,16.93 3481.19,151.66 3579.62,151.66 3644.97,217.02 J8.4@3644.97,245.56 3495.56,245.56 3481.19,259.93 R17.1@3367.02,259.93
NetJ8_5: J8.5 R16.1 U3.4 | length 3813
  Top Layer w6: U3.4@605.51,-550 655,-550 665,-560 665,-565 708.66,-608.66 708.66,-640.71 770.14,-702.19 2093.09,-702.19 2155.51,-639.76 3257.87,-639.76 3326.77,-570.87 3326.77,16.93 3367.02,57.18 R16.1@3367.02,181.19 3431.98,181.19 3446.35,195.56 J8.5@3544.97,195.56
NetJ9_1: J9.1 R19.1 U3.1 | length 3271.7
  Top Layer w6: U3.1@605.51,-700 709.84,-700 748.03,-738.19 3385.83,-738.19 3498.03,-625.98 R19.1@3498.03,-551.18 J9.1@3740.16,-551.18
NetR18_1: R18.1 U3.2 | length 3064.4
  Top Layer w6: U3.2@605.51,-650 679.53,-650 755.72,-726.19 3296.69,-726.19 3358.46,-664.42 3358.46,-489.97 3375.98,-472.44 R18.1@3431.1,-472.44
PECL_OUT: pad.0@400.79,-600 pad.0@400.79,-650 U1.Y22 U3.6 U3.7 | length 365.5
  Bottom Layer w6: U1.Y22@334.65,-413.39 334.65,-579.92 ; pad.0@400.79,-650 354.72,-650 334.65,-629.92 334.65,-579.92 ; pad.0@400.79,-600 354.73,-600 334.65,-579.92
PROG_B: pad.0@1219.49,167.32 pad.0@1600.39,731.3 R22.1 U1.B1 U7.7 | length 3617.6
  Top Layer w6: R22.1@1082.68,244.09 1142.72,244.09 ; pad.0@1219.49,167.32 1202,184.81 1202,199.97 1179.63,222.34 1164.47,222.34 1142.72,244.09 ; pad.0@1600.39,731.3 1635,696.69 1635,510 1665,480 1665,315 1670,310 1670,240 1645,215 1645,195 1625,175 1230,175 1222.32,167.32 1222.32,222.42 1200.65,244.09 1142.72,244.09
  Bottom Layer w6: U1.B1@-374.02,413.39 -374.02,614.17 -256.89,731.3 -254.17,731.3 -248.08,737.39 1575.84,737.39 1581.93,731.3 pad.0@1600.39,731.3 ; U7.7@1219.49,109.25 pad.0@1219.49,167.32
PROM_INIT_B: pad.0@1161.42,-258.46 pad.0@1273.62,-179.13 R20.1 U1.W17 U7.8 | length 1447.2
  Top Layer w6: R20.1@1161.42,-258.46 1240.75,-179.13 pad.0@1273.62,-179.13
  Bottom Layer w6: U1.W17@295.28,-216.54 314.96,-196.85 629.92,-196.85 730.32,-297.24 1122.64,-297.24 pad.0@1161.42,-258.46 ; U7.8@1245.08,109.25 1245.08,56.1 1253.94,47.24 1287.4,47.24 1314.96,19.69 1314.96,-165.35 1301.18,-179.13 pad.0@1273.62,-179.13
RECA0: J4.13 U1.V11 | length 758.4
  Top Layer w6: U1.V11@255.91,19.69 275.59,0 377.36,0 388.19,-10.83 388.19,-45.28 396.06,-53.15 589.96,-53.15 618.11,-25 925,-25 930.65,-19.35 J4.13@930.65,0
RECA1: J4.38 U1.Y11 | length 506.9
  Top Layer w6: U1.Y11@334.65,19.69 382.28,19.69 390.16,27.56 390.16,46.02 396.3,52.17 564.37,52.17 616.54,0 J4.38@795.65,0
RECA2: J4.15 U1.U11 | length 761
  Top Layer w6: U1.U11@216.54,19.69 236.22,39.37 309.45,39.37 322.24,52.17 361.61,52.17 387.21,77.76 682.24,77.76 685,75 925,75 930.65,80.65 J4.15@930.65,100
RECA3: J4.40 U1.W10 | length 517.3
  Top Layer w6: U1.W10@295.28,59.06 311.42,59.06 317.32,64.96 356.69,64.96 382.28,90.55 670.55,90.55 680,100 J4.40@795.65,100
RECA4: J4.17 U1.U10 | length 783.8
  Top Layer w6: U1.U10@216.54,59.06 228.74,59.06 248.43,78.74 270.08,78.74 282.87,91.54 300.59,91.54 328.15,119.09 654.09,119.09 710,175 925,175 930.65,180.65 J4.17@930.65,200
RECA5: J4.42 U1.V9 | length 581.8
  Top Layer w6: U1.V9@255.91,98.43 272.05,98.43 291.73,118.11 309.45,118.11 323.23,131.89 646.89,131.89 715,200 J4.42@795.65,200
RECA6: J4.19 U1.V8 | length 762.1
  Top Layer w6: U1.V8@255.91,137.8 275.59,157.48 632.48,157.48 720,245 720,260 735,275 925,275 930.65,280.65 J4.19@930.65,300
RECA7: J4.44 U1.W7 | length 579.3
  Top Layer w6: U1.W7@295.28,177.17 305.12,177.17 311.15,171.13 ; 312.01,170.28 311.15,171.13 ; J4.44@795.65,300 720,300 705,285 705,250 625.28,170.28 624.42,170.18 311.15,170.18 311.15,171.13
RECB0: J4.26 U1.Y21 | length 570.9
  Top Layer w6: U1.Y21@334.65,-374.02 346.46,-374.02 366.14,-354.33 484.33,-354.33 730,-600 J4.26@795.65,-600
RECB1: J4.3 U1.V19 | length 788.9
  Top Layer w6: U1.V19@255.91,-295.28 264.72,-295.28 290,-270 525,-270 730,-475 920,-475 930.65,-485.65 J4.3@930.65,-500
RECB2: J4.28 U1.U20 | length 689.2
  Top Layer w6: U1.U20@216.54,-334.65 236.22,-314.96 303.15,-314.96 333.66,-284.45 514.45,-284.45 730,-500 J4.28@795.65,-500
RECB3: J4.5 pad.0@1655,-455 U1.V17 U7.1 | length 2900.1
  Top Layer w6: U1.V17@255.91,-216.54 307.09,-216.54 327.76,-195.87 550.87,-195.87 730,-375 920,-375 930.65,-385.65 J4.5@930.65,-400 1260,-400 1335,-475 1635,-475 pad.0@1655,-455
  Bottom Layer w6: U7.1@1065.95,109.25 1065.95,150.59 1062.99,153.54 1062.99,198.82 1085.63,221.46 1268.54,221.46 1273.28,216.72 1282.22,216.72 1379,119.94 1379,111 1400,90 1455,90 1510,35 1510,-5 1535,-30 1570,-30 1705,-165 1780,-165 1795,-180 1795,-315 pad.0@1655,-455
RECB4: J4.30 U1.U18 | length 655.1
  Top Layer w6: U1.U18@216.54,-255.91 236.22,-236.22 566.22,-236.22 730,-400 J4.30@795.65,-400
RECB5: J4.7 U1.V15 | length 753.3
  Top Layer w6: U1.V15@255.91,-137.8 258.27,-137.8 277.95,-157.48 617.52,-157.48 735.04,-275 925,-275 930.65,-280.65 J4.7@930.65,-300
RECB6: J4.32 U1.W16 | length 558.6
  Top Layer w6: U1.W16@296.46,-178.35 U1.W16@295.28,-177.17 302.17,-170.28 595.28,-170.28 725,-300 J4.32@795.65,-300
RECB7: J4.9 U1.U14 | length 783.8
  Top Layer w6: U1.U14@216.54,-98.43 236.22,-78.74 269.69,-78.74 282.48,-91.54 300.2,-91.54 326.77,-118.11 678.11,-118.11 735,-175 925,-175 930.65,-180.65 J4.9@930.65,-200
RECC0: J5.46 U1.V3 | length 1381.4
  Top Layer w6: U1.V3@255.91,334.65 267.72,334.65 287.4,354.33 342.52,354.33 388.78,308.07 598.07,308.07 615,325 615,415 725,525 1005,525 1130,400 J5.46@1415.65,400
RECC1: J5.21 pad.0@1650,260 U1.Y7 | length 1617.3
  Top Layer w6: J5.21@1550.65,400 1615,400 1625,390 1625,285 pad.0@1650,260
  Bottom Layer w6: U1.Y7@334.65,177.17 354.33,196.85 691.85,196.85 695,200 970,200 1065.28,295.28 1505.91,295.28 1529.53,318.9 1591.1,318.9 pad.0@1650,260
RECC2: J5.44 U1.W5 | length 1271.5
  Top Layer w6: U1.W5@295.28,255.91 314.37,275 625,275 645,295 645,345 725,425 1087.8,425 1212.8,300 J5.44@1415.65,300
RECC3: J5.19 pad.0@1550.65,300 U1.Y8 | length 1283.2
  Bottom Layer w6: U1.Y8@334.65,137.8 354.33,157.48 667.48,157.48 695,185 975,185 1072.48,282.48 1533.13,282.48 pad.0@1550.65,300
RECC4: J5.42 U1.V7 | length 1310.5
  Top Layer w6: U1.V7@255.91,177.17 267.72,177.17 287.4,196.85 303.15,196.85 316.93,183.07 618.07,183.07 690,255 690,300 715,325 1170.08,325 1295.08,200 J5.42@1415.65,200
RECC5: J5.17 pad.0@1550.65,200 U1.W9 | length 1355.2
  Bottom Layer w6: U1.W9@295.28,98.43 314.96,118.11 648.11,118.11 700,170 980,170 1079.69,269.69 1480.97,269.69 pad.0@1550.65,200
RECC6: J5.40 U1.W8 | length 1234.6
  Top Layer w6: U1.W8@295.28,137.8 311.42,137.8 318.31,144.69 639.69,144.69 720,225 992.13,225 1006.78,210.34 1174.66,210.34 1190,195 1190,150 1240,100 J5.40@1415.65,100
RECC7: J5.15 pad.0@1550.65,100 U1.Y10 | length 1356.5
  Bottom Layer w6: U1.Y10@334.65,59.06 354.33,78.74 628.74,78.74 680,130 958.74,130 1075.79,247.05 1282.95,247.05 1289.28,240.72 1292.16,240.72 1403,129.88 1403,127 1405,125 1525.65,125 pad.0@1550.65,100
RECD0: J5.11 pad.0@1550.65,-100 U1.AA12 | length 1319
  Bottom Layer w6: U1.AA12@374.02,-19.69 393.7,0 606.3,0 791.34,-185.04 1188.98,-185.04 1203.94,-200 1228.03,-200 1240.03,-212 1334.97,-212 1346.97,-200 1450.65,-200 pad.0@1550.65,-100
RECD1: J5.34 U1.V13 | length 1218.1
  Top Layer w6: U1.V13@255.91,-59.06 267.72,-59.06 287.4,-78.74 368.5,-78.74 381.3,-91.54 676.54,-91.54 710,-125 1265,-125 1340,-200 J5.34@1415.65,-200
RECD2: J5.9 pad.0@1550.65,-200 U1.Y13 | length 1348.2
  Bottom Layer w6: U1.Y13@334.65,-59.06 354.33,-39.37 624.37,-39.37 690,-105 690,-169.29 721.5,-200.79 1185.04,-200.79 1197.84,-213.58 1224.64,-213.58 1235.06,-224 1339.94,-224 1350.36,-213.58 1537.07,-213.58 pad.0@1550.65,-200
RECD3: J5.32 U1.W15 | length 1220
  Top Layer w6: U1.W15@296.46,-138.98 U1.W15@295.28,-137.8 311.02,-137.8 316.93,-143.7 653.7,-143.7 735,-225 1105.32,-225 1120.08,-239.76 1120.08,-292.32 1127.76,-300 J5.32@1415.65,-300
RECD4: J5.7 pad.0@1630,-250 U1.W14 | length 1583.3
  Top Layer w6: J5.7@1550.65,-300 1620,-300 1630,-290 pad.0@1630,-250
  Bottom Layer w6: U1.W14@295.28,-98.43 314.96,-78.74 638.74,-78.74 675,-115 675,-185 703.58,-213.58 1179.13,-213.58 1195.55,-230 1224.09,-230 1230.09,-236 1344.91,-236 1350.91,-230 1610,-230 pad.0@1630,-250
RECD5: J5.30 U1.V16 | length 1263.5
  Top Layer w6: U1.V16@255.91,-177.17 267.72,-177.17 287.4,-196.85 303.15,-196.85 316.93,-183.07 588.07,-183.07 730,-325 1260,-325 1335,-400 J5.30@1415.65,-400
RECD6: J5.5 pad.0@1675,-270 U1.Y15 | length 1684.3
  Top Layer w6: J5.5@1550.65,-400 1645,-400 1665,-380 1665,-280 pad.0@1675,-270
  Bottom Layer w6: U1.Y15@334.65,-137.8 354.33,-118.11 588.11,-118.11 740,-270 1075.47,-270 1119.09,-226.38 1174.21,-226.38 1217.84,-270 pad.0@1675,-270
RECD7: J5.28 U1.U19 | length 1316.5
  Top Layer w6: U1.U19@216.54,-295.28 236.22,-275.59 265.75,-275.59 285.43,-255.91 565.91,-255.91 735,-425 1255,-425 1330,-500 J5.28@1415.65,-500
REFCLK: pad.0@400.79,600 U1.Y1 U2.7 | length 241.5
  Bottom Layer w6: U1.Y1@334.65,413.39 334.65,580.71 353.94,600 pad.0@400.79,600
REFCLK+: J4.49 pad.0@536.61,550 pad.1 R15.1 U2.1 | length 259
  Top Layer w6: U2.1@605.51,550 J4.49@795.65,550
  Bottom Layer w6: R15.1@536.61,550 pad.1@605.51,550
REFCLK-: J4.50 pad.0@536.61,650 pad.0@605.51,600 R14.1 U2.2 | length 301.5
  Top Layer w6: U2.2@605.91,600.39 795.65,600.39 J4.50@797.24,600.39
  Bottom Layer w6: R14.1@536.61,650 536.61,614.96 551.57,600 pad.0@605.51,600
RESETN: J4.1 U1.W21 | length 772.9
  Top Layer w6: U1.W21@295.28,-374.02 314.96,-354.33 342.52,-354.33 362.21,-334.65 494.65,-334.65 735,-575 925,-575 930.65,-580.65 J4.1@930.65,-600
RX_A: C42.2 U1.A5 | length 434.9
  Bottom Layer w6: C42.2@-801.77,324.8 -780.12,346.46 -740.16,346.46 -659.45,265.75 -423.23,265.75 U1.A5@-413.39,255.91
RX_B: C43.2 U1.A9 | length 400.6
  Bottom Layer w6: C43.2@-801.77,88.58 -782.09,108.27 -423.23,108.27 U1.A9@-413.39,98.43
RX_BC0_INT+: J3.38 pad.0@2013.78,39.37 R1.2 R7.1 | length 1096.5
  Top Layer w8: R7.1@1923.23,39.37 R1.2@2013.78,39.37
  Bottom Layer w6: pad.0@2013.78,39.37 2053.15,78.74 2913.39,78.74 2933.07,98.43 J3.38@2995.32,98.43
RX_BC0_INT-: J3.40 pad.0@2013.78,118.11 R3.2 R6.1 | length 1096.5
  Top Layer w8: R6.1@1923.23,118.11 R3.2@2013.78,118.11
  Bottom Layer w6: pad.0@2013.78,118.11 2033.46,137.8 2096.46,137.8 2116.14,118.11 2913.39,118.11 2933.07,137.8 J3.40@2995.32,137.8
RX_C: C47.2 U1.A15 | length 400.6
  Bottom Layer w6: C47.2@-801.77,-147.64 -782.09,-127.95 -423.23,-127.95 U1.A15@-413.39,-137.8
RX_CLK_INT+: J3.34 pad.0@2013.78,-118.11 R4.2 R8.1 | length 1146.5
  Top Layer w8: R8.1@1923.23,-118.11 R4.2@2013.78,-118.11
  Bottom Layer w6: pad.0@2013.78,-118.11 2047.24,-118.11 2106.3,-59.06 2106.3,-29.53 2135.83,0 2913.39,0 2933.07,19.69 J3.34@2995.32,19.69
RX_CLK_INT-: J3.36 pad.0@2013.78,-39.37 R2.2 R5.1 | length 1112.9
  Top Layer w8: R5.1@1923.23,-39.37 R2.2@2013.78,-39.37
  Bottom Layer w6: pad.0@2013.78,-39.37 2037.4,-39.37 2116.14,39.37 2913.39,39.37 2933.07,59.06 J3.36@2995.32,59.06
RX_D: C53.2 U1.A19 | length 433.2
  Bottom Layer w6: C53.2@-801.77,-383.86 -718.5,-383.86 -620.08,-285.43 -423.23,-285.43 U1.A19@-413.39,-295.28
SLB_ID: J3.30 U1.F4 | length 4186
  Bottom Layer w6: U1.F4@-216.54,295.28 -196.85,275.59 -196.85,-353 -194.85,-355 419.96,-355 431.96,-343 678.15,-343 752.15,-417 1485.15,-417 1543.15,-475 1686.15,-475 1839.15,-322 1839.15,-162.5 1852.65,-149 2087.15,-149 2118.15,-118 2118.15,-98.92 2138.15,-78.92 2853.97,-78.92 2873.84,-59.05 J3.30@2995.32,-59.05
SYNC1_0: J1.5 pad.0@2402.15,-545.5 U1.D22 | length 2978.5
  MidLayer3 w6: U1.D22@-295.28,-413.39 -190.32,-518.34 197.15,-518.34 222.15,-543.34 266.49,-543.34 343.15,-620 416.15,-620 564.15,-472 1606.15,-472 1692.15,-558 2150.15,-558 2194.49,-513.66 2370.31,-513.66 pad.0@2402.15,-545.5
  Bottom Layer w6: J1.5@2340.98,-531.5 2388.15,-531.5 pad.0@2402.15,-545.5
SYNC1_1: J1.6 pad.0@312.65,-476.5 pad.0@2254.15,-545 U1.C21 | length 2975.2
  MidLayer4 w6: pad.0@312.65,-476.5 343.15,-507 501.15,-507 632.15,-638 683.84,-638 700.84,-621 2129.15,-621 2160.15,-590 2209.15,-590 pad.0@2254.15,-545
  Bottom Layer w6: U1.C21@-334.65,-374.02 -354.85,-353.81 -354.85,-317 -352.85,-315 -237.85,-315 -236.85,-316 -236.85,-424 -184.35,-476.5 pad.0@312.65,-476.5 ; J1.6@2195.32,-531.5 2240.65,-531.5 pad.0@2254.15,-545
SYNC1_2: J1.7 pad.0@2133.65,-433 U1.J22 | length 2576.1
  MidLayer3 w6: U1.J22@-98.43,-413.39 -41.9,-469.91 220.72,-469.91 258.15,-507.34 343.49,-507.34 364.49,-486.34 417.65,-486.34 451.34,-452.66 513.27,-452.66 561.08,-404.84 2105.49,-404.84 pad.0@2133.65,-433
  Bottom Layer w6: pad.0@2133.65,-433 2249.15,-433 2250.15,-434 2250.15,-466.63 2275.65,-492.13 J1.7@2340.98,-492.13
SYNC1_3: J1.8 pad.0@2082.15,-472.4 U1.H22 | length 2470.1
  MidLayer3 w6: U1.H22@-137.8,-413.39 -69.18,-482 208.81,-482 246.15,-519.34 355.49,-519.34 375.84,-499 429.08,-499 463.08,-465 528.92,-465 575.92,-418 1829.15,-418 1832.15,-421 2065.65,-421 2082.15,-437.5 pad.0@2082.15,-472.4
  Bottom Layer w6: pad.0@2082.15,-472.4 2133.55,-472.4 2153.28,-492.13 J1.8@2195.32,-492.13
SYNC1_4: J1.9 pad.0@2275.15,-436.5 U1.W22 | length 2137
  MidLayer2 w6: U1.W22@295.28,-413.39 314.54,-413.39 375.49,-474.34 409.81,-474.34 500.31,-383.84 2222.49,-383.84 pad.0@2275.15,-436.5
  Bottom Layer w6: pad.0@2275.15,-436.5 2291.41,-452.76 J1.9@2340.98,-452.76
SYNC1_5: J1.10 pad.0@388.15,-455.5 U1.V22 | length 2075.5
  MidLayer2 w6: U1.V22@255.91,-413.39 276.29,-393 325.65,-393 pad.0@388.15,-455.5
  Bottom Layer w6: pad.0@388.15,-455.5 531.65,-455.5 653.15,-577 1788.15,-577 1879.15,-486 2027.15,-486 2060.39,-452.76 J1.10@2195.32,-452.76
SYNC1_6: J1.11 pad.0@2407.4,-406.75 U1.J21 | length 2678.3
  MidLayer3 w6: U1.J21@-98.43,-374.02 -15.44,-457 231.81,-457 270.15,-495.34 331.49,-495.34 352.49,-474.34 405.55,-474.34 439.89,-440 505.15,-440 553.15,-392 2256.18,-392 2261.18,-387 2387.65,-387 pad.0@2407.4,-406.75
  Bottom Layer w6: J1.11@2340.98,-413.39 2400.76,-413.39 pad.0@2407.4,-406.75
SYNC1_7: J1.12 pad.0@1942.15,-324 U1.H21 | length 3330.7
  MidLayer4 w6: U1.H21@-137.8,-374.02 -156.78,-393 -387.85,-393 -399.35,-381.5 -399.35,-84.5 -392.85,-78 486.15,-78 703.15,-295 1582.15,-295 1639.15,-352 1914.15,-352 pad.0@1942.15,-324
  Bottom Layer w6: pad.0@1942.15,-324 2031.54,-413.39 J1.12@2195.32,-413.39
SYNC1_8: J1.13 pad.0@531.15,-648 pad.0@2422.15,-478 U1.V21 | length 2884.8
  MidLayer3 w6: pad.0@531.15,-648 673.84,-648 707.84,-614 2097.15,-614 2120.15,-591 2384.15,-591 2422.15,-553 pad.0@2422.15,-478
  MidLayer4 w6: U1.V21@255.91,-374.02 236.92,-393 160.15,-393 157.15,-396 157.15,-562.5 175.65,-581 474.49,-581 531.15,-637.66 pad.0@531.15,-648
  Bottom Layer w6: J1.13@2340.98,-374.02 2422.67,-374.02 2427.15,-378.5 2427.15,-473 pad.0@2422.15,-478
SYNC2_0: J1.14 pad.0@2271.65,-362 U1.P21 | length 2320
  MidLayer3 w6: U1.P21@98.43,-374.02 118.41,-394 486.15,-394 553.15,-327 1248.15,-327 1301.15,-380 2249.87,-380 2267.87,-362 pad.0@2271.65,-362
  Bottom Layer w6: J1.14@2195.32,-374.02 2259.63,-374.02 pad.0@2271.65,-362
SYNC2_1: J1.15 pad.0@2262.23,-334.65 U1.J20 | length 2565.9
  MidLayer3 w6: U1.J20@-98.43,-334.65 -78.07,-355 194.15,-355 196.15,-353 196.15,-278 198.15,-276 749.88,-276 785.88,-312 1604.15,-312 1647.49,-355.34 2241.54,-355.34 pad.0@2262.23,-334.65
  Bottom Layer w6: pad.0@2262.23,-334.65 J1.15@2340.98,-334.65
SYNC2_2: J1.16 pad.0@2108.15,-334 U1.T20 | length 2091.6
  MidLayer4 w6: U1.T20@177.17,-334.65 196.81,-315 519.28,-315 607.28,-403 2039.15,-403 pad.0@2108.15,-334
  Bottom Layer w6: pad.0@2108.15,-334 2108.8,-334.65 J1.16@2195.32,-334.65
SYNC2_3: J1.17 pad.0@2279.15,-406 U1.P20 | length 2761.9
  MIdLayer5 w6: U1.P20@98.43,-334.65 118.78,-355 387.65,-355 460.65,-428 623.15,-428 667.15,-384 2257.15,-384 pad.0@2279.15,-406
  Bottom Layer w6: pad.0@2279.15,-406 2266.86,-393.71 2121.15,-393.71 2087.15,-359.71 2087.15,-319.71 2091.86,-315 2246.15,-315 2265.87,-295.28 J1.17@2340.98,-295.28
SYNC2_4: J1.18 pad.0@2061.15,-291 U1.K19 | length 2336.6
  MIdLayer5 w6: U1.K19@-59.06,-295.28 -39.78,-276 523.15,-276 574.15,-327 1276.15,-327 1320.15,-371 1981.15,-371 pad.0@2061.15,-291
  Bottom Layer w6: pad.0@2061.15,-291 2065.43,-295.28 J1.18@2195.32,-295.28
SYNC2_5: J1.19 pad.0@2257.56,-255.91 U1.L19 | length 2624
  MidLayer3 w6: U1.L19@-19.69,-295.28 78.15,-197.44 78.15,-81 81.15,-78 378.15,-78 499.15,-199 1347.49,-199 1365.49,-181 1569.15,-181 1597.15,-209 1907.46,-209 1927.46,-189 1975.84,-189 1998.84,-212 2213.65,-212 pad.0@2257.56,-255.91
  Bottom Layer w6: pad.0@2257.56,-255.91 J1.19@2340.98,-255.91
SYNC2_6: J1.20 pad.0@1990.15,-305 U1.R18 | length 2157.8
  MIdLayer5 w6: U1.R18@137.8,-255.91 157.7,-236 538.15,-236 611.65,-309.5 1592.65,-309.5 1640.15,-357 1938.15,-357 pad.0@1990.15,-305
  Bottom Layer w6: pad.0@1990.15,-305 2039.24,-255.91 J1.20@2195.32,-255.91
SYNC2_7: J1.21 pad.0@146.15,-29 pad.0@2280.15,-315 U1.K4 | length 3205.6
  MIdLayer5 w6: pad.0@146.15,-29 146.15,-141 163.15,-158 670.55,-158 804.55,-292 1624.15,-292 1677.15,-345 1872.8,-345 1946.49,-271.32 2079.15,-271.32 2122.83,-315 pad.0@2280.15,-315
  Bottom Layer w6: U1.K4@-59.06,295.28 -38.78,275 150,275 157.48,267.52 157.48,-17.67 pad.0@146.15,-29 ; pad.0@2280.15,-315 2397.81,-315 2425.15,-287.66 2425.15,-241.03 2400.65,-216.53 J1.21@2340.98,-216.53
SYNC2_8: J1.22 pad.0@475.15,-374 pad.0@1945.4,-208.75 U1.N19 | length 2303.7
  MidLayer2 w6: pad.0@475.15,-374 549.15,-300 892.15,-300 1047.15,-145 1199.65,-145 1275.9,-221.25 1932.9,-221.25 pad.0@1945.4,-208.75
  MIdLayer5 w6: U1.N19@59.06,-295.28 78.78,-315 416.15,-315 pad.0@475.15,-374
  Bottom Layer w6: pad.0@1945.4,-208.75 1953.18,-216.53 J1.22@2195.32,-216.53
